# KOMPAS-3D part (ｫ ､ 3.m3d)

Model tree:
1. Эскиз:1
2. Операция выдавливания:1
     Расстояние 1 = 20
3. Эскиз:2
4. Операция выдавливания:2
     Расстояние 1 = 400
5. Эскиз:3
6. Вырезать элемент выдавливания:1
     Расстояние 1 = 70
7. Эскиз:4
8. Вырезать элемент выдавливания:2
     Расстояние 1 = 2
9. Эскиз:5
10. Эскиз:11
11. Вырезать элемент выдавливания:7
     Расстояние 1 = 30
12. Операция выдавливания:3
     Расстояние 1 = 16.96
13. Эскиз:13
14. Вырезать элемент выдавливания:9
     Расстояние 1 = 70
15. Эскиз:14
16. Вырезать элемент выдавливания:10
     Расстояние 1 = 80
